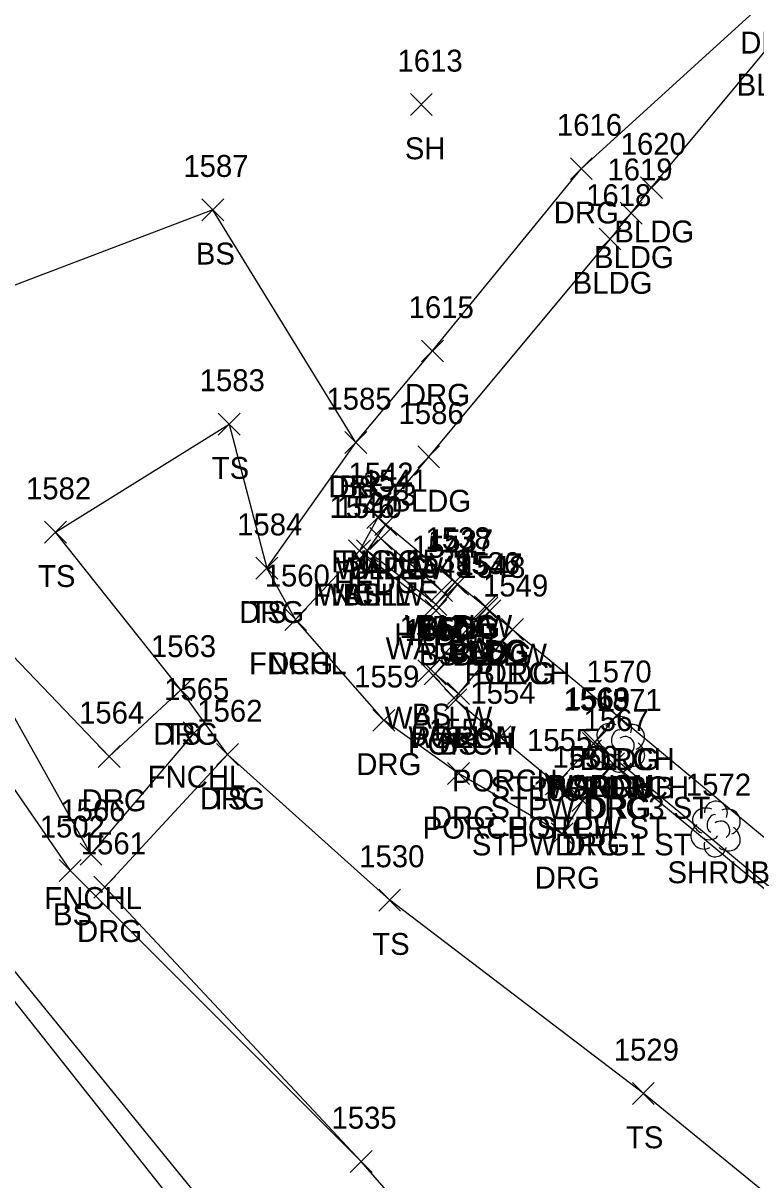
# Model space of a CAD drawing. Extents: x 1505656 to 1508446, y 700805 to 703031.
# Drawn here: x 1506389.2 to 1506456, y 702088 to 702193.6 of the extents above; entities that cross this region are included whole.
import ezdxf

# ---------------------------------------------------------------- set-up
doc = ezdxf.new("R2010")
doc.units = 0
for name, color, linetype in [('L_A', 7, 'Continuous'), ('L_I', 7, 'Continuous'), ('L_TIC', 7, 'Continuous'), ('LAHR', 7, 'Continuous'), ('LBC', 7, 'Continuous'), ('LBF', 7, 'Continuous'), ('LELB', 7, 'Continuous'), ('LFNC', 7, 'Continuous'), ('LSH', 7, 'Continuous'), ('LW', 7, 'Continuous'), ('PET', 7, 'Continuous'), ('R_A', 7, 'Continuous'), ('R_I', 7, 'Continuous'), ('R_TIC', 7, 'Continuous'), ('RDG', 7, 'Continuous')]:
    doc.layers.add(name, color=color, linetype=linetype)

msp = doc.modelspace()

# ---------------------------------------------------------------- linework, layer by layer
at = {"layer": 'L_TIC'}
for points in [[(1506424.51, 702185.16), (1506426.51, 702187.16)], [(1506426.51, 702185.16), (1506424.51, 702187.16)], [(1506445.52, 702177.57), (1506447.52, 702179.57)], [(1506447.52, 702177.57), (1506445.52, 702179.57)], [(1506405.49, 702175.55), (1506407.49, 702177.55)], [(1506407.49, 702175.55), (1506405.49, 702177.55)], [(1506443.67, 702175.23), (1506445.67, 702177.23)], [(1506445.67, 702175.23), (1506443.67, 702177.23)], [(1506441.73, 702172.88), (1506443.73, 702174.88)], [(1506443.73, 702172.88), (1506441.73, 702174.88)], [(1506406.97, 702155.99), (1506408.97, 702157.99)], [(1506408.97, 702155.99), (1506406.97, 702157.99)], [(1506418.54, 702154.3), (1506420.54, 702156.3)], [(1506420.54, 702154.3), (1506418.54, 702156.3)], [(1506425.18, 702152.99), (1506427.18, 702154.99)], [(1506427.18, 702152.99), (1506425.18, 702154.99)], [(1506420.54, 702147.47), (1506422.54, 702149.47)], [(1506422.54, 702147.47), (1506420.54, 702149.47)], [(1506420.54, 702147.47), (1506422.54, 702149.47)], [(1506422.54, 702147.47), (1506420.54, 702149.47)], [(1506421.28, 702146.82), (1506423.28, 702148.82)], [(1506423.28, 702146.82), (1506421.28, 702148.82)], [(1506421.28, 702146.82), (1506423.28, 702148.82)], [(1506423.28, 702146.82), (1506421.28, 702148.82)], [(1506391.12, 702146.12), (1506393.12, 702148.12)], [(1506393.12, 702146.12), (1506391.12, 702148.12)], [(1506420.82, 702145.55), (1506422.82, 702147.55)], [(1506422.82, 702145.55), (1506420.82, 702147.55)], [(1506418.87, 702144.43), (1506420.87, 702146.43)], [(1506420.87, 702144.43), (1506418.87, 702146.43)], [(1506418.87, 702144.43), (1506420.87, 702146.43)], [(1506420.87, 702144.43), (1506418.87, 702146.43)], [(1506419.58, 702144.42), (1506421.58, 702146.42)], [(1506421.58, 702144.42), (1506419.58, 702146.42)], [(1506410.4, 702142.83), (1506412.4, 702144.83)], [(1506412.4, 702142.83), (1506410.4, 702144.83)], [(1506427.58, 702141.57), (1506429.58, 702143.57)], [(1506429.58, 702141.57), (1506427.58, 702143.57)], [(1506427.58, 702141.57), (1506429.58, 702143.57)], [(1506429.58, 702141.57), (1506427.58, 702143.57)], [(1506426.34, 702140.79), (1506428.34, 702142.79)], [(1506428.34, 702140.79), (1506426.34, 702142.79)], [(1506427.82, 702141.37), (1506429.82, 702143.37)], [(1506429.82, 702141.37), (1506427.82, 702143.37)], [(1506427.82, 702141.37), (1506429.82, 702143.37)], [(1506429.82, 702141.37), (1506427.82, 702143.37)], [(1506425.84, 702139.53), (1506427.84, 702141.53)], [(1506427.84, 702139.53), (1506425.84, 702141.53)], [(1506430.32, 702139.3), (1506432.32, 702141.3)], [(1506432.32, 702139.3), (1506430.32, 702141.3)], [(1506430.32, 702139.3), (1506432.32, 702141.3)], [(1506432.32, 702139.3), (1506430.32, 702141.3)], [(1506425.85, 702138.97), (1506427.85, 702140.97)], [(1506427.85, 702138.97), (1506425.85, 702140.97)], [(1506430.49, 702139.2), (1506432.49, 702141.2)], [(1506432.49, 702139.2), (1506430.49, 702141.2)], [(1506430.49, 702139.2), (1506432.49, 702141.2)], [(1506432.49, 702139.2), (1506430.49, 702141.2)], [(1506430.75, 702138.95), (1506432.75, 702140.95)], [(1506432.75, 702138.95), (1506430.75, 702140.95)], [(1506430.75, 702138.95), (1506432.75, 702140.95)], [(1506432.75, 702138.95), (1506430.75, 702140.95)], [(1506413.04, 702138.16), (1506415.04, 702140.16)], [(1506415.04, 702138.16), (1506413.04, 702140.16)], [(1506432.84, 702137.25), (1506434.84, 702139.25)], [(1506434.84, 702137.25), (1506432.84, 702139.25)], [(1506432.84, 702137.25), (1506434.84, 702139.25)], [(1506434.84, 702137.25), (1506432.84, 702139.25)], [(1506425.2, 702133.47), (1506427.2, 702135.47)], [(1506427.2, 702133.47), (1506425.2, 702135.47)], [(1506425.77, 702133.19), (1506427.77, 702135.19)], [(1506427.77, 702133.19), (1506425.77, 702135.19)], [(1506402.57, 702131.72), (1506404.57, 702133.72)], [(1506404.57, 702131.72), (1506402.57, 702133.72)], [(1506427.91, 702131.41), (1506429.91, 702133.41)], [(1506429.91, 702131.41), (1506427.91, 702133.41)], [(1506427.91, 702131.41), (1506429.91, 702133.41)], [(1506429.91, 702131.41), (1506427.91, 702133.41)], [(1506427.66, 702130.82), (1506429.66, 702132.82)], [(1506429.66, 702130.82), (1506427.66, 702132.82)], [(1506427.66, 702130.82), (1506429.66, 702132.82)], [(1506429.66, 702130.82), (1506427.66, 702132.82)], [(1506442.36, 702129.41), (1506444.36, 702131.41)], [(1506444.36, 702129.41), (1506442.36, 702131.41)], [(1506442.36, 702129.41), (1506444.36, 702131.41)], [(1506444.36, 702129.41), (1506442.36, 702131.41)], [(1506403.78, 702127.8), (1506405.78, 702129.8)], [(1506405.78, 702127.8), (1506403.78, 702129.8)], [(1506431.67, 702127.46), (1506433.67, 702129.46)], [(1506433.67, 702127.46), (1506431.67, 702129.46)], [(1506440.21, 702126.84), (1506442.21, 702128.84)], [(1506442.21, 702126.84), (1506440.21, 702128.84)], [(1506440.21, 702126.84), (1506442.21, 702128.84)], [(1506442.21, 702126.84), (1506440.21, 702128.84)], [(1506440.36, 702126.95), (1506442.36, 702128.95)], [(1506442.36, 702126.95), (1506440.36, 702128.95)], [(1506440.36, 702126.95), (1506442.36, 702128.95)], [(1506442.36, 702126.95), (1506440.36, 702128.95)], [(1506406.81, 702125.82), (1506408.81, 702127.82)], [(1506408.81, 702125.82), (1506406.81, 702127.82)], [(1506442.05, 702124.97), (1506444.05, 702126.97)], [(1506444.05, 702124.97), (1506442.05, 702126.97)], [(1506436.84, 702123.15), (1506438.84, 702125.15)], [(1506438.84, 702123.15), (1506436.84, 702125.15)], [(1506436.84, 702123.15), (1506438.84, 702125.15)], [(1506438.84, 702123.15), (1506436.84, 702125.15)], [(1506439.23, 702121.62), (1506441.23, 702123.62)], [(1506441.23, 702121.62), (1506439.23, 702123.62)], [(1506394.36, 702116.73), (1506396.36, 702118.73)], [(1506396.36, 702116.73), (1506394.36, 702118.73)], [(1506392.45, 702115.25), (1506394.45, 702117.25)], [(1506394.45, 702115.25), (1506392.45, 702117.25)], [(1506421.62, 702112.54), (1506423.62, 702114.54)], [(1506423.62, 702112.54), (1506421.62, 702114.54)], [(1506421.62, 702112.54), (1506423.62, 702114.54)], [(1506423.62, 702112.54), (1506421.62, 702114.54)], [(1506444.77, 702094.89), (1506446.77, 702096.89)], [(1506446.77, 702094.89), (1506444.77, 702096.89)], [(1506419.01, 702088.68), (1506421.01, 702090.68)], [(1506421.01, 702088.68), (1506419.01, 702090.68)]]:
    msp.add_lwpolyline(points, dxfattribs=at)
at = {"layer": 'LAHR'}
msp.add_lwpolyline([(1506421.82, 702146.55), (1506427.34, 702141.79)], dxfattribs=at)
at = {"layer": 'LBC'}
for points in [[(1506431.32, 702140.3), (1506428.82, 702142.37), (1506428.58, 702142.57), (1506422.28, 702147.82), (1506421.54, 702148.47), (1506426.18, 702153.99), (1506442.73, 702173.88), (1506444.67, 702176.23), (1506446.52, 702178.57), (1506457.68, 702191.96), (1506459.85, 702190.18), (1506468.89, 702182.65), (1506479.6, 702173.52), (1506475.02, 702167.7), (1506467.11, 702158.3), (1506459.39, 702149.08), (1506489.89, 702123.69)], [(1506431.32, 702140.3), (1506431.49, 702140.2), (1506431.75, 702139.95), (1506433.84, 702138.25), (1506443.36, 702130.41), (1506473.47, 702105.48), (1506473.94, 702105.04), (1506474.14, 702104.91), (1506481.66, 702113.75), (1506482.03, 702114.03), (1506486.94, 702119.95), (1506487.3, 702120.42), (1506489.89, 702123.69)]]:
    msp.add_lwpolyline(points, dxfattribs=at)
at = {"layer": 'LBF'}
for points in [[(1506433.84, 702138.25), (1506428.91, 702132.41), (1506428.66, 702131.82), (1506432.67, 702128.46), (1506437.84, 702124.15), (1506441.21, 702127.84), (1506441.36, 702127.95), (1506443.36, 702130.41)], [(1506437.84, 702124.15), (1506440.23, 702122.62), (1506443.05, 702125.97), (1506441.21, 702127.84)]]:
    msp.add_lwpolyline(points, dxfattribs=at)
at = {"layer": 'LELB'}
for points in [[(1506136.16, 702495.92), (1506139.06, 702485.98), (1506162.22, 702449.9), (1506191.43, 702407.7), (1506214.6, 702372.19), (1506239.69, 702335.52), (1506257.04, 702310.4), (1506264.9, 702297.23), (1506293.72, 702260.69), (1506306.57, 702243.03), (1506315.16, 702227.11), (1506327.91, 702209.16), (1506338.97, 702195.32), (1506348.16, 702183.95), (1506374.02, 702144.46), (1506393.45, 702116.25), (1506420.01, 702089.68)], [(1506156.37, 702446.43), (1506184.16, 702403.93), (1506208.77, 702367.29), (1506232.27, 702331.6), (1506257.88, 702293.76), (1506284.65, 702254.18), (1506307.32, 702222.26), (1506327.16, 702194.17), (1506337.75, 702176.5), (1506365.45, 702137.46), (1506385.38, 702110.7), (1506412.37, 702077.53), (1506428.22, 702062.69), (1506438.31, 702049.85), (1506449, 702037.53), (1506458.55, 702033.77), (1506467.09, 702033.53), (1506475.87, 702037.86), (1506484.72, 702048.28), (1506486.52, 702060.25), (1506466.84, 702078.7), (1506445.77, 702095.89), (1506422.62, 702113.54), (1506407.81, 702126.82)], [(1506419.54, 702155.3), (1506406.49, 702176.55), (1506373.11, 702163.86)], [(1506403.57, 702132.72), (1506392.12, 702147.12), (1506407.97, 702156.99), (1506411.4, 702143.83)], [(1506428.82, 702142.37), (1506426.85, 702139.97), (1506419.87, 702145.43)], [(1506431.49, 702140.2), (1506426.2, 702134.47), (1506428.66, 702131.82)]]:
    msp.add_lwpolyline(points, dxfattribs=at)
at = {"layer": 'LFNC'}
for points in [[(1506404.78, 702128.8), (1506395.36, 702117.73), (1506383.9, 702138.16), (1506370.28, 702161.28), (1506361.24, 702178.8), (1506352.89, 702196.54), (1506359.41, 702213.98), (1506368.12, 702232.5), (1506396.58, 702269.17), (1506405.46, 702278.13), (1506422.05, 702293.03), (1506443.83, 702311.16), (1506467.22, 702329.6), (1506489.51, 702310.58), (1506505.88, 702295.55), (1506523.06, 702279.47), (1506548.22, 702255.09), (1506585.71, 702218.69), (1506600.72, 702203.5)], [(1506421.54, 702148.47), (1506419.87, 702145.43), (1506414.04, 702139.16)]]:
    msp.add_lwpolyline(points, dxfattribs=at)
at = {"layer": 'LSH'}
for p, q in [((1506443.62, 702127.81), (1506443.62, 702127.81)), ((1506443.62, 702127.81), (1506443.62, 702127.81)), ((1506452.34, 702120.08), (1506452.34, 702120.08)), ((1506452.34, 702120.08), (1506452.34, 702120.08))]:
    msp.add_line(p, q, dxfattribs=at)
for centre in [(1506443.66, 702129.24), (1506452.39, 702121.52)]:
    msp.add_arc(centre, 1.05, 335.5272, 180.9563, dxfattribs=at)
for centre, major_axis, ratio, start_param, end_param in [((1506442.82, 702128.47), (1.21, -0.51), 0.895232, 1.570796, 4.712389), ((1506444.66, 702128.39), (-1.14, -0.48), 0.949671, 1.570796, 4.712389), ((1506443.41, 702128.27), (-0.208, -0.792), 0.645439, 3.141593, 6.283185), ((1506442.53, 702127.1), (0.58, -1.04), 0.959034, 3.141593, 6.283185), ((1506444.12, 702127.64), (-0.5, 0.667), 0.989748, 3.141593, 6.283185), ((1506444.62, 702126.97), (-1.09, 0.79), 0.841452, 1.570796, 4.712389), ((1506443.62, 702126.31), (0.26, 1.06), 0.942809, 1.570796, 4.712389), ((1506443.16, 702127.06), (-0.625, -0.083), 0.423636, 0, 3.141593), ((1506451.55, 702120.75), (1.21, -0.51), 0.895232, 1.570796, 4.712389), ((1506452.14, 702120.54), (-0.208, -0.792), 0.645439, 3.141593, 6.283185), ((1506453.39, 702120.67), (-1.14, -0.48), 0.949671, 1.570796, 4.712389), ((1506451.26, 702119.38), (0.58, -1.04), 0.959034, 3.141593, 6.283185), ((1506452.84, 702119.92), (-0.5, 0.667), 0.989748, 3.141593, 6.283185), ((1506451.89, 702119.33), (-0.625, -0.083), 0.423636, 0, 3.141593), ((1506453.34, 702119.25), (-1.09, 0.79), 0.841452, 1.570796, 4.712389), ((1506452.34, 702118.58), (0.26, 1.06), 0.942809, 1.570796, 4.712389)]:
    msp.add_ellipse(centre, major_axis=major_axis, ratio=ratio, start_param=start_param, end_param=end_param, dxfattribs=at)
at = {"layer": 'LW'}
for points in [[(1506428.58, 702142.57), (1506426.84, 702140.53), (1506420.58, 702145.42), (1506422.28, 702147.82)], [(1506431.75, 702139.95), (1506426.77, 702134.19), (1506428.91, 702132.41)], [(1506441.36, 702127.95), (1506471.44, 702103.04), (1506473.47, 702105.48)]]:
    msp.add_lwpolyline(points, dxfattribs=at)
at = {"layer": 'PET'}
msp.add_lwpolyline([(1506206.75, 702365.83), (1506229.99, 702330.47), (1506255.88, 702291.81), (1506281.67, 702252.74), (1506303.79, 702220.03), (1506334.98, 702175.13), (1506363.75, 702135.87), (1506383.85, 702109.99), (1506410.96, 702075.76), (1506431.3, 702052.09), (1506450.65, 702029.2), (1506469.42, 702008.91), (1506504.12, 701976.85), (1506522.63, 701959.5), (1506561.3, 701928.76), (1506582.88, 701911.4)], dxfattribs=at)
at = {"layer": 'R_TIC'}
for points in [[(1506439.11, 702179.3), (1506441.11, 702181.3)], [(1506441.11, 702179.3), (1506439.11, 702181.3)], [(1506425.52, 702162.66), (1506427.52, 702164.66)], [(1506427.52, 702162.66), (1506425.52, 702164.66)], [(1506418.54, 702154.3), (1506420.54, 702156.3)], [(1506420.54, 702154.3), (1506418.54, 702156.3)], [(1506410.4, 702142.83), (1506412.4, 702144.83)], [(1506412.4, 702142.83), (1506410.4, 702144.83)], [(1506413.04, 702138.16), (1506415.04, 702140.16)], [(1506415.04, 702138.16), (1506413.04, 702140.16)], [(1506402.57, 702131.72), (1506404.57, 702133.72)], [(1506404.57, 702131.72), (1506402.57, 702133.72)], [(1506421.09, 702128.95), (1506423.09, 702130.95)], [(1506423.09, 702128.95), (1506421.09, 702130.95)], [(1506396.01, 702125.65), (1506398.01, 702127.65)], [(1506398.01, 702125.65), (1506396.01, 702127.65)], [(1506406.81, 702125.82), (1506408.81, 702127.82)], [(1506408.81, 702125.82), (1506406.81, 702127.82)], [(1506442.05, 702124.97), (1506444.05, 702126.97)], [(1506444.05, 702124.97), (1506442.05, 702126.97)], [(1506427.89, 702124.1), (1506429.89, 702126.1)], [(1506429.89, 702124.1), (1506427.89, 702126.1)], [(1506439.23, 702121.62), (1506441.23, 702123.62)], [(1506441.23, 702121.62), (1506439.23, 702123.62)], [(1506437.37, 702118.59), (1506439.37, 702120.59)], [(1506439.37, 702118.59), (1506437.37, 702120.59)], [(1506395.61, 702113.72), (1506397.61, 702115.72)], [(1506397.61, 702113.72), (1506395.61, 702115.72)], [(1506419.01, 702088.68), (1506421.01, 702090.68)], [(1506421.01, 702088.68), (1506419.01, 702090.68)]]:
    msp.add_lwpolyline(points, dxfattribs=at)
at = {"layer": 'RDG'}
for points in [[(1506467.15, 702044.28), (1506454.96, 702052.84), (1506438.53, 702068.48), (1506420.01, 702089.68), (1506396.61, 702114.72), (1506407.81, 702126.82), (1506403.57, 702132.72), (1506397.01, 702126.65), (1506385.48, 702138.66), (1506373.11, 702163.86), (1506354.57, 702195.8), (1506363.45, 702213.22), (1506370.89, 702223.45), (1506376.82, 702230.29), (1506393.45, 702217), (1506418.82, 702248.86), (1506438.37, 702232.02), (1506443.53, 702227.34), (1506453.6, 702221.01), (1506468.75, 702213.14)], [(1506440.23, 702122.62), (1506438.37, 702119.59), (1506428.89, 702125.1), (1506422.09, 702129.95), (1506414.04, 702139.16), (1506411.4, 702143.83), (1506419.54, 702155.3), (1506426.52, 702163.66), (1506440.11, 702180.3), (1506457.12, 702195.81), (1506463.22, 702193.78), (1506459.85, 702190.18)], [(1506443.05, 702125.97), (1506471.44, 702102.48), (1506473.94, 702105.04)]]:
    msp.add_lwpolyline(points, dxfattribs=at)

# ---------------------------------------------------------------- texts
at = {"layer": 'L_A'}
for s, p in [('BLDG', (1506454.28, 702186.96)), ('SH', (1506424, 702181.16)), ('BLDG', (1506443.12, 702173.57)), ('BS', (1506404.93, 702171.55)), ('BLDG', (1506441.26, 702171.23)), ('BLDG', (1506439.32, 702168.88)), ('TS', (1506406.38, 702151.99)), ('BS', (1506417.98, 702150.3)), ('BLDG', (1506422.77, 702148.99)), ('FNCHL', (1506417.29, 702143.47)), ('WALLW', (1506417.7, 702142.82)), ('BLDG', (1506418.13, 702143.47)), ('BLDG', (1506418.87, 702142.82)), ('TS', (1506390.53, 702142.12)), ('HEDGE', (1506417.52, 702141.55)), ('FNCHL', (1506415.62, 702140.43)), ('WALLW', (1506415.99, 702140.42)), ('BS', (1506418.31, 702140.43)), ('TS', (1506409.81, 702138.83)), ('WALLW', (1506424, 702137.57)), ('BLDG', (1506425.17, 702137.57)), ('BLDG', (1506425.41, 702137.37)), ('BS', (1506427.26, 702137.37)), ('HEDGE', (1506423.04, 702136.79)), ('WALLW', (1506422.25, 702135.53)), ('BLDG', (1506427.92, 702135.3)), ('BLDG', (1506427.92, 702135.3)), ('BLDG', (1506428.08, 702135.2)), ('BS', (1506429.93, 702135.2)), ('FNCHL', (1506409.79, 702134.16)), ('BS', (1506425.29, 702134.97)), ('WALLW', (1506427.17, 702134.95)), ('BLDG', (1506428.34, 702134.95)), ('PORCH', (1506429.46, 702133.25)), ('BLDG', (1506430.43, 702133.25)), ('WALLW', (1506422.18, 702129.19)), ('BS', (1506424.64, 702129.47)), ('TS', (1506401.98, 702127.72)), ('WALLW', (1506424.33, 702127.41)), ('PORCH', (1506424.28, 702126.82)), ('PORCH', (1506424.54, 702127.41)), ('BS', (1506427.1, 702126.82)), ('PORCH', (1506438.98, 702125.41)), ('BLDG', (1506439.95, 702125.41)), ('FNCHL', (1506400.53, 702123.8)), ('PORCH', (1506428.3, 702123.46)), ('STPW PORCH', (1506431.82, 702122.84)), ('WALLW', (1506436.78, 702122.95)), ('PORCH', (1506436.83, 702122.84)), ('PORCH', (1506436.99, 702122.95)), ('SHRUB', (1506439.25, 702122.81)), ('TS', (1506406.21, 702121.82)), ('STPW DRG3 ST', (1506431.81, 702120.97)), ('PORCH STPW ST', (1506425.63, 702119.15)), ('PORCH', (1506433.46, 702119.15)), ('STPW DRG1 ST', (1506430.12, 702117.62)), ('SHRUB', (1506447.97, 702115.08)), ('FNCHL', (1506391.1, 702112.73)), ('BS', (1506391.89, 702111.25)), ('TS', (1506421.03, 702108.54)), ('TS', (1506421.03, 702108.54)), ('TS', (1506444.18, 702090.89))]:
    msp.add_text(s, height=2, dxfattribs=at).set_placement(p)
at = {"layer": 'L_I'}
for s, p in [('1613', (1506423.33, 702189.16)), ('1620', (1506443.7, 702181.57)), ('1587', (1506403.79, 702179.55)), ('1619', (1506442.49, 702179.23)), ('1618', (1506440.55, 702176.88)), ('1583', (1506405.28, 702159.99)), ('1585', (1506416.85, 702158.3)), ('1586', (1506423.43, 702156.99)), ('1542', (1506418.85, 702151.47)), ('1542', (1506418.85, 702151.47)), ('1582', (1506389.43, 702150.12)), ('1541', (1506420.15, 702150.82)), ('1541', (1506420.15, 702150.82)), ('1543', (1506419.13, 702149.55)), ('1546', (1506417.12, 702148.43)), ('1546', (1506417.12, 702148.43)), ('1540', (1506417.8, 702148.42)), ('1584', (1506408.7, 702146.83)), ('1544', (1506424.65, 702144.79)), ('1538', (1506425.89, 702145.57)), ('1538', (1506425.89, 702145.57)), ('1537', (1506426.12, 702145.37)), ('1537', (1506426.12, 702145.37)), ('1539', (1506424.14, 702143.53)), ('1545', (1506424.15, 702142.97)), ('1536', (1506428.58, 702143.3)), ('1536', (1506428.58, 702143.3)), ('1547', (1506428.8, 702143.2)), ('1547', (1506428.8, 702143.2)), ('1548', (1506429.06, 702142.95)), ('1548', (1506429.06, 702142.95)), ('1560', (1506411.21, 702142.16)), ('1549', (1506431.14, 702141.25)), ('1549', (1506431.14, 702141.25)), ('1552', (1506423.51, 702137.47)), ('1550', (1506423.99, 702137.19)), ('1563', (1506400.83, 702135.72)), ('1551', (1506426.79, 702135.41)), ('1551', (1506426.79, 702135.41)), ('1553', (1506425.96, 702134.82)), ('1553', (1506425.96, 702134.82)), ('1570', (1506440.58, 702133.41)), ('1570', (1506440.58, 702133.41)), ('1565', (1506402.04, 702131.8)), ('1554', (1506429.98, 702131.46)), ('1568', (1506438.47, 702130.84)), ('1568', (1506438.47, 702130.84)), ('1569', (1506438.62, 702130.95)), ('1569', (1506438.62, 702130.95)), ('1562', (1506405.06, 702129.82)), ('1571', (1506441.49, 702130.81)), ('1567', (1506440.31, 702128.97)), ('1555', (1506435.15, 702127.15)), ('1555', (1506435.15, 702127.15)), ('1556', (1506437.48, 702125.62)), ('1572', (1506449.65, 702123.08)), ('1566', (1506392.56, 702120.73)), ('1502', (1506390.68, 702119.25)), ('1530', (1506419.84, 702116.54)), ('1530', (1506419.84, 702116.54)), ('1529', (1506443.07, 702098.89)), ('1535', (1506417.31, 702092.68))]:
    msp.add_text(s, height=2, dxfattribs=at).set_placement(p)
at = {"layer": 'R_A'}
for p in [(1506454.61, 702190.81), (1506437.59, 702175.3), (1506424.01, 702158.66), (1506417.03, 702150.3), (1506408.88, 702138.83), (1506411.53, 702134.16), (1506401.05, 702127.72), (1506419.57, 702124.95), (1506394.5, 702121.65), (1506405.29, 702121.82), (1506440.54, 702120.97), (1506426.38, 702120.1), (1506437.71, 702117.62), (1506435.86, 702114.59), (1506394.09, 702109.72)]:
    msp.add_text('DRG', height=2, dxfattribs=at).set_placement(p)
at = {"layer": 'R_I'}
for s, p in [('1616', (1506437.88, 702183.3)), ('1615', (1506424.35, 702166.66)), ('1585', (1506416.85, 702158.3)), ('1584', (1506408.7, 702146.83)), ('1560', (1506411.21, 702142.16)), ('1563', (1506400.83, 702135.72)), ('1559', (1506419.38, 702132.95)), ('1562', (1506405.06, 702129.82)), ('1564', (1506394.27, 702129.65)), ('1567', (1506440.31, 702128.97)), ('1558', (1506426.2, 702128.1)), ('1556', (1506437.48, 702125.62)), ('1557', (1506435.68, 702122.59)), ('1561', (1506394.43, 702117.72)), ('1535', (1506417.31, 702092.68))]:
    msp.add_text(s, height=2, dxfattribs=at).set_placement(p)

doc.saveas('drawing.dxf')
